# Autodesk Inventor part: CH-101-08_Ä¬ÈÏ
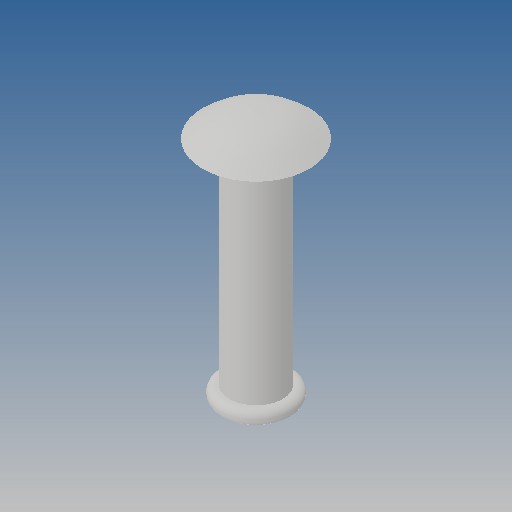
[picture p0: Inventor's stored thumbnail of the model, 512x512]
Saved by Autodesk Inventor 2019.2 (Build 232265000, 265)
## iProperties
Created: 2010-06
Part Number: CH-101-08_Ä¬ÈÏ
Material: Ogólny
Document SubType Name: Modeling
Designer: CADENGINEERING4
Density: 1 g/cm^3
Appearance: Domyślna
Author: CADENGINEERING4
Revision Number: ÈÎºÎ
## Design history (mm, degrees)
feature "NONE"
node "Bryła1"
